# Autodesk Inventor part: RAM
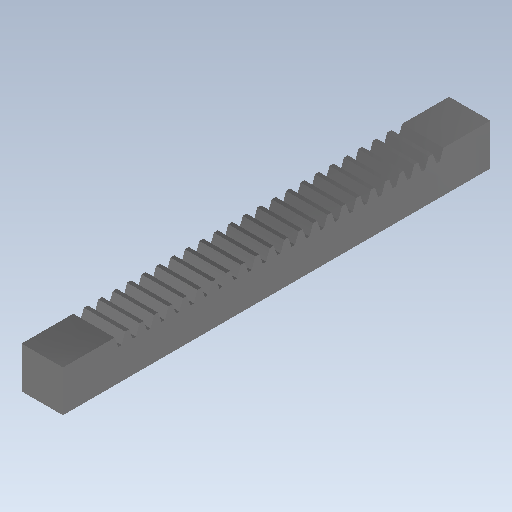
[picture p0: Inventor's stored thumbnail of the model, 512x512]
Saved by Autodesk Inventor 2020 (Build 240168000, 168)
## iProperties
Part Number: RAM
Document SubType Name: Modeling
Created: 2003-11
Designer: Autodesk, Inc.
Manufacturer: Standard
Standards Organization: Custom
Mass: 510.413 g
Surface Area: 178.528 cm^2
Volume: 65.0208 cm^3
Density: 7.85 g/cm^3
Material: Steel, High Strength Low Alloy
Appearance: Chrome
Control State: 0
Master: False
Checked Out: False
Shininess: 64.0
Length Units: 11272
Angle Units: 11279
Time Units: 11290
Mass Units: 11286
Length Display Precision: 3
Angle Display Precision: 2
Compacted: True
Density: 0.0
Volumn: 0.0
Area: 0.0
PropertySet Name: Model Information
Author: Autodesk, Inc.
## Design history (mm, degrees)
sketch "Sketch1"
  geometry: L1 (0, 0)-(19.05, 0); L2 (19.05, 0)-(19.05, 19.05); L3 (19.05, 19.05)-(0, 19.05); L4 (0, 19.05)-(0, 0)
  constraints: 8 end point, 2 parallel, 1 horizontal, 1 perpendicular
  dimensions: "d0" = 19.05 distance of L1.start L1.end; "d1" = 19.05 distance of L1.end L2.end
extrude "Extrusion1" new body sketch "Sketch1" distance "d2" = 196.85; taper "d3" = 0 deg
sketch "Sketch2"
  geometry: L1 (0, 0)-(0, 19.05) reference; L2 (0, 19.05)-(-196.85, 19.05) reference; L3 (-196.85, 19.05)-(-196.85, 0) reference; L4 (0, 0)-(-196.85, 0) reference; L5 (-168.185, 19.05)-(-166.4, 19.05); L6 (-166.4, 19.05)-(-164.739, 14.486); L7 (-168.185, 19.05)-(-169.846, 14.486); L8 (-167.293, 19.05)-(-167.293, 27.541); L9 (-130.145, 19.823)-(-130.145, 4.561); L10 (-173.431, 16.934)-(-94.815, 16.934); L11 (-163.197, 14.486)-(-161.535, 19.05); L12 (-161.535, 19.05)-(-159.751, 19.05); L13 (-159.751, 19.05)-(-158.089, 14.486); L14 (-164.739, 14.486)-(-163.197, 14.486); L15 (-158.089, 14.486)-(-24.993, 14.486); L16 (-160.643, 19.05)-(-160.643, 25.268); L17 (-169.846, 14.486)-(-171.389, 14.486); L18 (-171.389, 14.486)-(-173.05, 19.05); L19 (-156.542, 14.486)-(-154.881, 19.05); L20 (-154.881, 19.05)-(-153.096, 19.05); L21 (-153.096, 19.05)-(-151.435, 14.486); L22 (-149.887, 14.486)-(-148.226, 19.05); L23 (-148.226, 19.05)-(-146.441, 19.05); L24 (-146.441, 19.05)-(-144.78, 14.486); L25 (-143.232, 14.486)-(-141.571, 19.05); L26 (-141.571, 19.05)-(-139.786, 19.05); L27 (-139.786, 19.05)-(-138.125, 14.486); L28 (-136.578, 14.486)-(-134.916, 19.05); L29 (-134.916, 19.05)-(-133.132, 19.05); L30 (-133.132, 19.05)-(-131.47, 14.486); L31 (-129.923, 14.486)-(-128.261, 19.05); L32 (-128.261, 19.05)-(-126.477, 19.05); L33 (-126.477, 19.05)-(-124.815, 14.486); L34 (-123.268, 14.486)-(-121.607, 19.05); L35 (-121.607, 19.05)-(-119.822, 19.05); L36 (-119.822, 19.05)-(-118.161, 14.486); L37 (-116.613, 14.486)-(-114.952, 19.05); L38 (-114.952, 19.05)-(-113.167, 19.05); L39 (-113.167, 19.05)-(-111.506, 14.486); L40 (-109.958, 14.486)-(-108.297, 19.05); L41 (-108.297, 19.05)-(-106.512, 19.05); L42 (-106.512, 19.05)-(-104.851, 14.486); L43 (-103.304, 14.486)-(-101.642, 19.05); L44 (-101.642, 19.05)-(-99.858, 19.05); L45 (-99.858, 19.05)-(-98.196, 14.486); L46 (-96.649, 14.486)-(-94.987, 19.05); L47 (-94.987, 19.05)-(-93.203, 19.05); L48 (-93.203, 19.05)-(-91.541, 14.486); L49 (-89.994, 14.486)-(-88.333, 19.05); L50 (-88.333, 19.05)-(-86.548, 19.05); L51 (-86.548, 19.05)-(-84.887, 14.486); L52 (-83.339, 14.486)-(-81.678, 19.05); L53 (-81.678, 19.05)-(-79.893, 19.05); L54 (-79.893, 19.05)-(-78.232, 14.486); L55 (-76.684, 14.486)-(-75.023, 19.05); L56 (-75.023, 19.05)-(-73.238, 19.05); L57 (-73.238, 19.05)-(-71.577, 14.486); L58 (-70.03, 14.486)-(-68.368, 19.05); L59 (-68.368, 19.05)-(-66.584, 19.05); L60 (-66.584, 19.05)-(-64.922, 14.486); L61 (-63.375, 14.486)-(-61.713, 19.05); L62 (-61.713, 19.05)-(-59.929, 19.05); L63 (-59.929, 19.05)-(-58.267, 14.486); L64 (-56.72, 14.486)-(-55.059, 19.05)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; 65 further points
  constraints: 201 end point, 53 point on line, 27 collinear, 10 parallel, 3 perpendicular, 2 midpoint, 1 coincident, 1 horizontal, 200 other
  dimensions: "d5" = 2.11582 distance between parallel lines of L10 L5; "d6" = 20 deg angle of L8 L7; "d7" = 20 deg angle of L6 L8; "d11" = 6.64972 distance between parallel lines of L16 L8; "d12" = 3.32486 distance of point (-165.63, 16.934) point (-168.955, 16.934); "d13" = 3.32486 distance of point (-158.981, 16.934) point (-162.306, 16.934) (= d12); "d14" = 3.32486 distance of point (-168.955, 16.934) point (-172.28, 16.934) (= d12); "d15" = 23.7998 distance from line of L3 L18.end; "d16" = 2.44856 distance between parallel lines of L17 L10; "d19" = 6.6548 distance of L11.start L19.start
extrude "Extrusion2" sketch "Sketch2" extent not by distance; stored distance "d24" = 25.4; taper "d25" = 0 deg
sketch "Sketch5"
  geometry: L1 (126.82, 14.486)-(128.482, 19.05) reference; L2 (125.273, 14.486)-(126.82, 14.486) reference; L3 (123.612, 19.05)-(125.273, 14.486) reference; L4 (123.612, 19.05)-(121.827, 19.05) reference; L5 (120.166, 14.486)-(121.827, 19.05) reference; L6 (118.618, 14.486)-(120.166, 14.486) reference; L7 (116.957, 19.05)-(118.618, 14.486) reference; L8 (116.957, 19.05)-(115.172, 19.05) reference; L9 (113.511, 14.486)-(115.172, 19.05) reference; L10 (111.963, 14.486)-(113.511, 14.486) reference; L11 (110.302, 19.05)-(111.963, 14.486) reference; L12 (110.302, 19.05)-(108.517, 19.05) reference; L13 (106.856, 14.486)-(108.517, 19.05) reference; L14 (105.309, 14.486)-(106.856, 14.486) reference; L15 (103.647, 19.05)-(105.309, 14.486) reference; L16 (103.647, 19.05)-(101.863, 19.05) reference; L17 (100.201, 14.486)-(101.863, 19.05) reference; L18 (98.654, 14.486)-(100.201, 14.486) reference; L19 (96.992, 19.05)-(98.654, 14.486) reference; L20 (96.992, 19.05)-(95.208, 19.05) reference; L21 (93.546, 14.486)-(95.208, 19.05) reference; L22 (91.999, 14.486)-(93.546, 14.486) reference; L23 (90.338, 19.05)-(91.999, 14.486) reference; L24 (90.338, 19.05)-(88.553, 19.05) reference; L25 (86.892, 14.486)-(88.553, 19.05) reference; L26 (85.344, 14.486)-(86.892, 14.486) reference; L27 (83.683, 19.05)-(85.344, 14.486) reference; L28 (83.683, 19.05)-(81.898, 19.05) reference; L29 (80.237, 14.486)-(81.898, 19.05) reference; L30 (78.689, 14.486)-(80.237, 14.486) reference; L31 (77.028, 19.05)-(78.689, 14.486) reference; L32 (77.028, 19.05)-(75.243, 19.05) reference; L33 (73.582, 14.486)-(75.243, 19.05) reference; L34 (72.035, 14.486)-(73.582, 14.486) reference; L35 (70.373, 19.05)-(72.035, 14.486) reference; L36 (70.373, 19.05)-(68.589, 19.05) reference; L37 (66.927, 14.486)-(68.589, 19.05) reference; L38 (65.38, 14.486)-(66.927, 14.486) reference; L39 (63.718, 19.05)-(65.38, 14.486) reference; L40 (63.718, 19.05)-(61.934, 19.05) reference; L41 (60.272, 14.486)-(61.934, 19.05) reference; L42 (58.725, 14.486)-(60.272, 14.486) reference; L43 (57.064, 19.05)-(58.725, 14.486) reference; L44 (57.064, 19.05)-(55.279, 19.05) reference; L45 (53.618, 14.486)-(55.279, 19.05) reference; L46 (52.07, 14.486)-(53.618, 14.486) reference; L47 (50.409, 19.05)-(52.07, 14.486) reference; L48 (50.409, 19.05)-(48.624, 19.05) reference; L49 (46.963, 14.486)-(48.624, 19.05) reference; L50 (45.415, 14.486)-(46.963, 14.486) reference; L51 (43.754, 19.05)-(45.415, 14.486) reference; L52 (43.754, 19.05)-(41.969, 19.05) reference; L53 (40.308, 14.486)-(41.969, 19.05) reference; L54 (38.761, 14.486)-(40.308, 14.486) reference; L55 (37.099, 19.05)-(38.761, 14.486) reference; L56 (37.099, 19.05)-(35.315, 19.05) reference; L57 (33.653, 14.486)-(35.315, 19.05) reference; L58 (32.111, 14.486)-(33.653, 14.486) reference; L59 (30.45, 19.05)-(32.111, 14.486) reference; L60 (30.45, 19.05)-(28.665, 19.05) reference; L61 (27.004, 14.486)-(28.665, 19.05) reference; L62 (25.461, 14.486)-(27.004, 14.486) reference; L63 (23.8, 19.05)-(25.461, 14.486) reference; L64 (23.8, 19.05)-(0, 19.05) reference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
  constraints: 10 end point, 3 parallel, 2 collinear, 2 point on line
  dimensions: "d26" = 1.5494 distance of L94.end L95.end; "d27" = 1.905 distance of L68.end L93.end
extrude "Extrusion3" cut sketch "Sketch5" distance "d28" = 25.4; taper "d29" = 0 deg
body "Solid1"
node "Projected Loop1"
node "Projected Loop4"
other parameters: "d22" = 25.4
